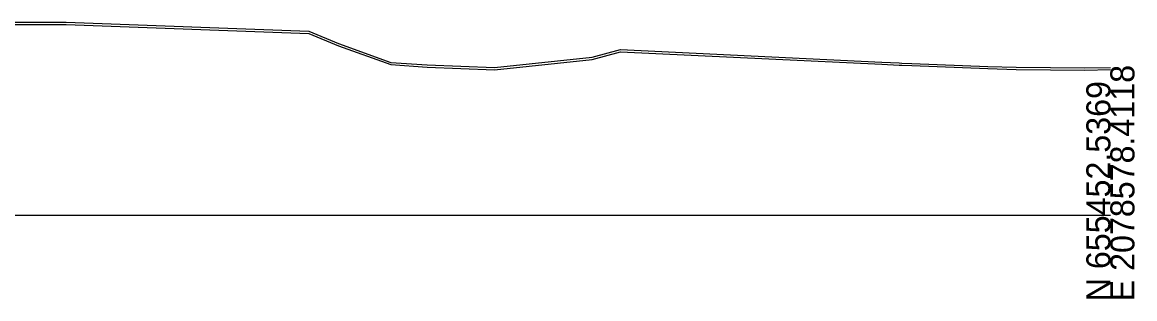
# Model space of a CAD drawing. Extents: x 1131015 to 1136271, y 133453 to 174329.
# Drawn here: x 1131513.8 to 1131643.3, y 155158 to 155190.1 of the extents above; entities that cross this region are included whole.
import ezdxf

# ---------------------------------------------------------------- set-up
doc = ezdxf.new("R2010")
doc.units = 0
for name, color, linetype in [('DESIGN - SHEET - Light Grid', 7, 'Continuous'), ('SURVEY - GROUND - Bottom of Topsoil Layer', 7, 'Continuous'), ('SURVEY - GROUND - Top of Ground', 7, 'Continuous')]:
    doc.layers.add(name, color=color, linetype=linetype)

msp = doc.modelspace()

# ---------------------------------------------------------------- linework, layer by layer
at = {"layer": 'DESIGN - SHEET - Light Grid'}
msp.add_line((1131340.46, 155167.66), (1131640.46, 155167.66), dxfattribs=at)
at = {"layer": 'SURVEY - GROUND - Bottom of Topsoil Layer'}
for p, q in [((1131501.09, 155189.85), (1131518.9, 155189.85)), ((1131518.9, 155189.85), (1131547.15, 155188.81)), ((1131547.15, 155188.81), (1131550.62, 155187.38)), ((1131550.62, 155187.38), (1131556.7, 155185.18)), ((1131580.15, 155185.79), (1131583.44, 155186.68)), ((1131583.44, 155186.68), (1131613.85, 155185.23)), ((1131556.7, 155185.18), (1131560.95, 155184.9)), ((1131560.95, 155184.9), (1131568.78, 155184.59)), ((1131568.78, 155184.59), (1131580.15, 155185.79)), ((1131613.85, 155185.23), (1131615.89, 155185.12)), ((1131615.89, 155185.12), (1131616.2, 155185.11)), ((1131616.2, 155185.11), (1131617.33, 155185.06)), ((1131617.33, 155185.06), (1131626.2, 155184.71)), ((1131626.2, 155184.71), (1131629.51, 155184.63)), ((1131629.51, 155184.63), (1131637.47, 155184.55)), ((1131637.47, 155184.55), (1131640.46, 155184.6))]:
    msp.add_line(p, q, dxfattribs=at)
at = {"layer": 'SURVEY - GROUND - Top of Ground'}
for p, q in [((1131501.09, 155190.1), (1131518.9, 155190.1)), ((1131518.9, 155190.1), (1131547.15, 155189.06)), ((1131547.15, 155189.06), (1131550.62, 155187.63)), ((1131550.62, 155187.63), (1131556.7, 155185.43)), ((1131568.78, 155184.84), (1131580.15, 155186.04)), ((1131580.15, 155186.04), (1131583.44, 155186.93)), ((1131583.44, 155186.93), (1131613.85, 155185.48)), ((1131556.7, 155185.43), (1131560.95, 155185.15)), ((1131560.95, 155185.15), (1131568.78, 155184.84)), ((1131613.85, 155185.48), (1131615.89, 155185.37)), ((1131615.89, 155185.37), (1131616.2, 155185.36)), ((1131616.2, 155185.36), (1131617.33, 155185.31)), ((1131617.33, 155185.31), (1131626.2, 155184.96)), ((1131626.2, 155184.96), (1131629.51, 155184.88)), ((1131629.51, 155184.88), (1131637.47, 155184.8)), ((1131637.47, 155184.8), (1131640.46, 155184.85))]:
    msp.add_line(p, q, dxfattribs=at)

# ---------------------------------------------------------------- texts
at = {"layer": 'DESIGN - SHEET - Light Grid'}
for s, p in [('E 2078578.4118', (1131643.26, 155157.66)), ('N 655452.5369', (1131640.46, 155157.66))]:
    msp.add_text(s, height=2.8, rotation=90, dxfattribs=at).set_placement(p)

doc.saveas('drawing.dxf')
